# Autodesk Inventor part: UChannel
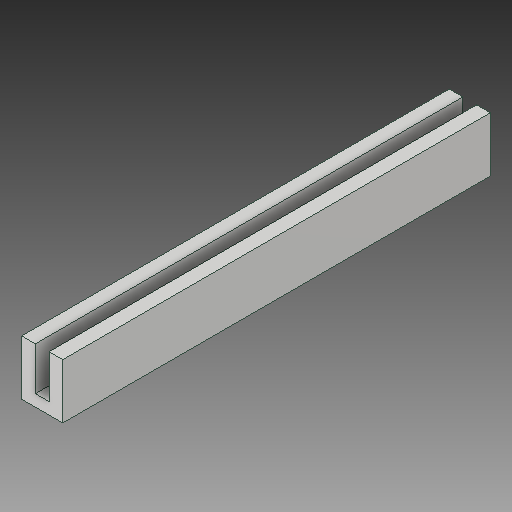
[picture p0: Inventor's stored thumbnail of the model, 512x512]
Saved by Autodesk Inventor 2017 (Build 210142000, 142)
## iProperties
Created: 2017-05
Part Number: UChannel
Material: Generic
Document SubType Name: Modeling
Designer: Savy
Density: 1 g/cm^3
Appearance: Default
Author: Savy
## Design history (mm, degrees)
feature "SOLID1"
body "Solid1"
